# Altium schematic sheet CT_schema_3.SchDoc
size 276 x 169 mm
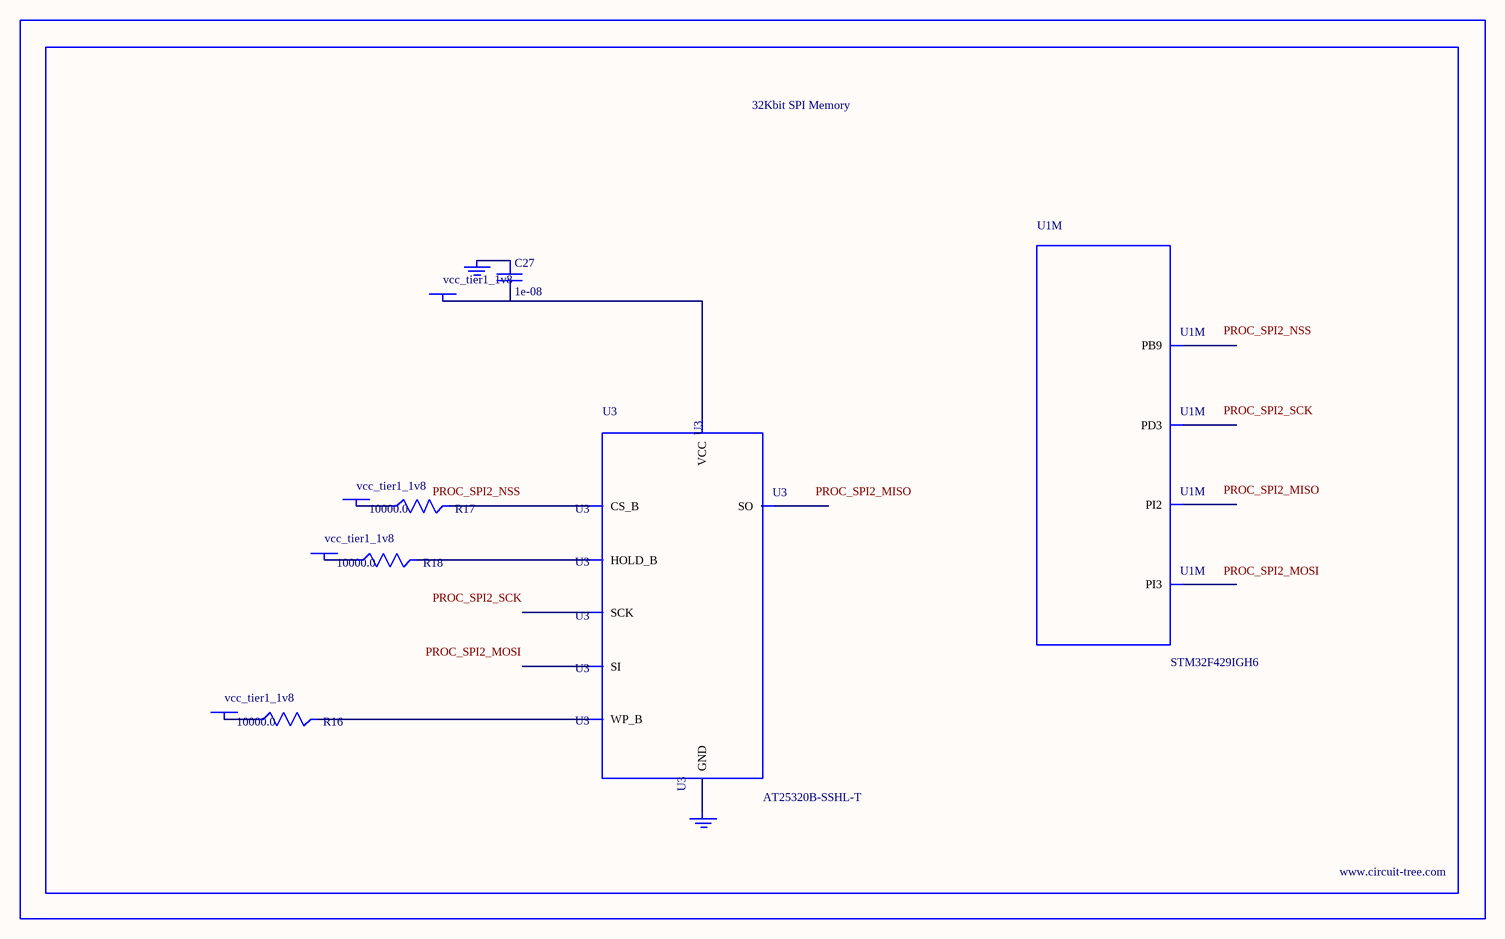
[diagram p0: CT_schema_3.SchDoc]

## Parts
BORDER2  (no value)
C27  1e-08  [C0402]
GND_INSTANCE_2_0  (no value)
GND_INSTANCE_2_1  (no value)
POWER_INSTANCE_2_0  vcc_tier1_1v8
POWER_INSTANCE_2_1  vcc_tier1_1v8
POWER_INSTANCE_2_2  vcc_tier1_1v8
POWER_INSTANCE_2_3  vcc_tier1_1v8
R16  10000.0  [R0603]
R17  10000.0  [R0603]
R18  10000.0  [R0603]
U1  STM32F429IGH6  [UFBGA176_25]  (part M of 15)
U3  AT25320B-SSHL-T  [SOIC-8]

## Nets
NetC27_1: C27.1 GND_INSTANCE_2_0.0(GND)
NetC27_2: C27.2 POWER_INSTANCE_2_3.0(PWR) U3.8(VCC)
NetGND_INSTANCE_2_1_0: GND_INSTANCE_2_1.0(GND) U3.4(GND)
NetPOWER_INSTANCE_2_0_0: POWER_INSTANCE_2_0.0(PWR) R17.1
NetPOWER_INSTANCE_2_1_0: POWER_INSTANCE_2_1.0(PWR) R16.1
NetPOWER_INSTANCE_2_2_0: POWER_INSTANCE_2_2.0(PWR) R18.1
NetR16_2: R16.2 U3.3(WP_B)
NetR17_2: R17.2 U3.1(CS_B)
NetR18_2: R18.2 U3.7(HOLD_B)

Not connected (* = marked no-connect by the designer): U1 B4(PB9) C13(PI3) C14(PI2) D11(PD3); U3 2(SO) 5(SI) 6(SCK)

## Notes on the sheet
- Labels drawn without touching a wire or pin: PROC_SPI2_MISO, PROC_SPI2_MOSI, PROC_SPI2_NSS, PROC_SPI2_SCK

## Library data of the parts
BORDER2 = BORDER_PAGE2
C27 = C0402C103K3RAC
GND_INSTANCE_2_0 GND_INSTANCE_2_1 = GND
POWER_INSTANCE_2_0-POWER_INSTANCE_2_3 = PWR
R16-R18 = RC0603JR-0710KL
